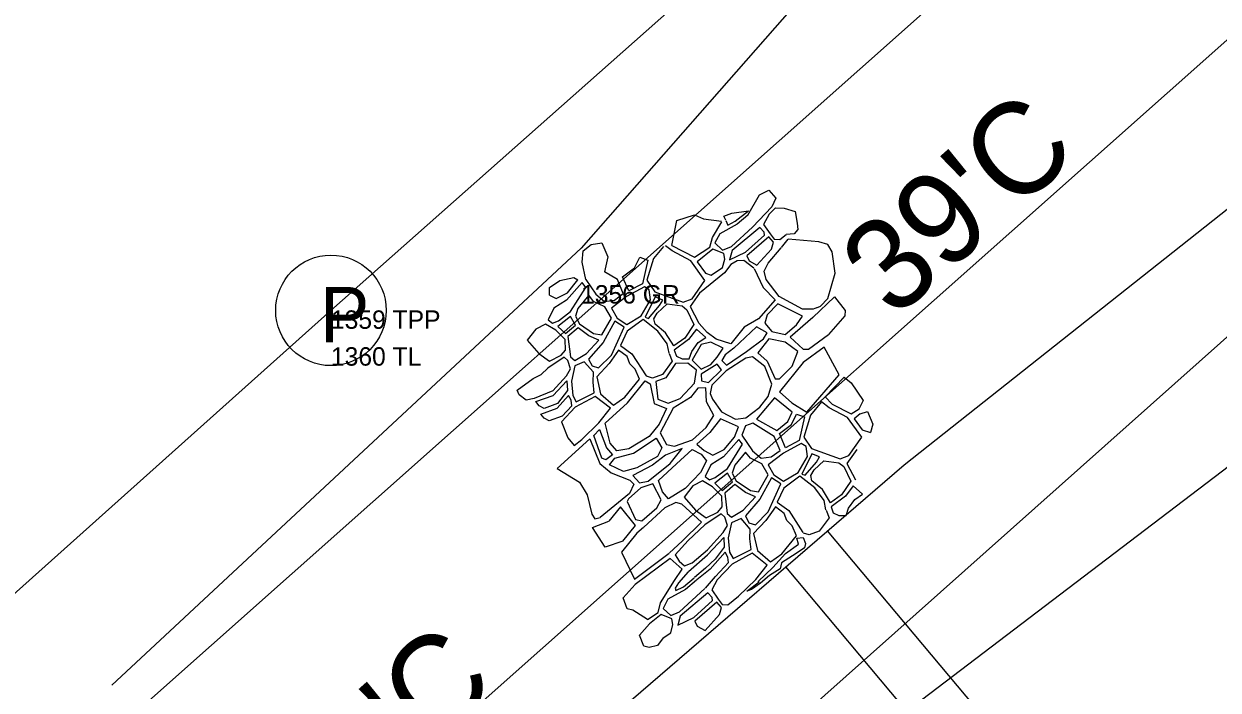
# Model space of a CAD drawing. Extents: x 50001 to 56005, y 49075 to 53926.
# Drawn here: x 53878.2 to 53943.1, y 51891.3 to 51927.5 of the extents above; entities that cross this region are included whole.
import ezdxf

# ---------------------------------------------------------------- set-up
doc = ezdxf.new("R2010")
doc.units = 0
for name, color, linetype in [('Level 1', 7, 'Continuous'), ('Level 11', 7, 'Continuous'), ('Level 16', 7, 'Continuous'), ('Level 18', 7, 'Continuous'), ('Level 3', 7, 'Continuous'), ('Level 57', 7, 'Continuous'), ('Level 59', 7, 'Continuous'), ('Level 61', 7, 'Continuous'), ('Level 7', 7, 'Continuous'), ('Level 8', 7, 'Continuous'), ('Level 9', 7, 'Continuous')]:
    doc.layers.add(name, color=color, linetype=linetype)

# ---------------------------------------------------------------- blocks, each defined once
blk = doc.blocks.new('TPP')
at = {"layer": 'Level 9'}
blk.add_circle((0, 0), 3, dxfattribs=at)
blk.add_text('P', height=3, dxfattribs=at).set_placement((-0.589, -1.729))

msp = doc.modelspace()

# ---------------------------------------------------------------- linework, layer by layer
at = {"layer": 'Level 1'}
msp.add_line((52544.807, 50683.302), (55534.583, 53340.862), dxfattribs=at)
at = {"layer": 'Level 11'}
for p, q in [((53894.91, 51911.927), (54324.203, 52292.615)), ((53424.495, 51490.929), (53894.91, 51911.927))]:
    msp.add_line(p, q, dxfattribs=at)
at = {"layer": 'Level 16'}
for p, q in [((53919.586, 51898.734), (53920.281, 51899.24)), ((53920.202, 51899.556), (53920.533, 51899.603)), ((53920.281, 51899.24), (53920.202, 51899.556)), ((53920.533, 51899.603), (53920.66, 51899.272)), ((53920.66, 51899.272), (53920.612, 51899.034)), ((53918.891, 51897.96), (53919.586, 51898.734)), ((53920.154, 51898.734), (53919.76, 51898.466)), ((53920.612, 51899.034), (53920.154, 51898.734)), ((53918.102, 51897.201), (53918.891, 51897.96)), ((53919.365, 51898.213), (53919.286, 51897.897)), ((53919.76, 51898.466), (53919.365, 51898.213)), ((53918.718, 51897.533), (53918.228, 51897.106)), ((53919.286, 51897.897), (53918.718, 51897.533)), ((53917.486, 51896.68), (53918.149, 51897.185)), ((53917.739, 51896.774), (53917.486, 51896.68)), ((53918.228, 51897.106), (53917.739, 51896.774)), ((53918.149, 51897.185), (53918.102, 51897.201))]:
    msp.add_line(p, q, dxfattribs=at)
for points in [[(53917.54, 51917.09), (53918.174, 51918.207), (53918.683, 51918.453), (53919.065, 51918.029), (53918.846, 51917.556), (53917.785, 51916.441)], [(53919.03, 51917.497), (53918.695, 51917.144), (53918.393, 51916.596), (53918.75, 51916.083), (53918.962, 51915.804), (53919.274, 51915.782), (53919.611, 51916.054)], [(53919.03, 51917.497), (53919.516, 51917.475), (53920.113, 51917.29), (53920.212, 51916.672), (53920.253, 51916.324), (53920.043, 51916.091), (53919.611, 51916.054)], [(53913.408, 51915.456), (53913.683, 51916.814), (53914.645, 51917.123), (53915.139, 51916.896), (53916.114, 51916.77)], [(53913.408, 51915.456), (53914.636, 51914.813), (53915.482, 51915.366), (53915.618, 51915.893), (53916.133, 51916.729)], [(53917.54, 51917.09), (53916.966, 51916.605), (53916.01, 51916.089), (53915.752, 51915.587), (53916.168, 51915.195), (53916.646, 51915.404), (53917.785, 51916.441)], [(53916.34, 51916.835), (53916.291, 51916.931), (53916.234, 51917.05), (53916.662, 51917.206), (53917.566, 51917.34)], [(53916.34, 51916.805), (53916.403, 51916.678), (53916.451, 51916.555), (53916.856, 51916.764), (53917.566, 51917.34)], [(53917.526, 51917.314), (53917.457, 51917.254)], [(53908.741, 51913.602), (53908.551, 51914.54), (53908.596, 51915.164), (53909.026, 51915.498), (53909.615, 51915.591), (53909.936, 51914.833), (53909.757, 51914.03)], [(53912.952, 51915.391), (53912.419, 51914.75), (53912.062, 51913.561), (53912.49, 51912.936), (53914.033, 51912.375), (53914.511, 51912.559), (53915.211, 51913.552), (53914.44, 51914.617), (53913.436, 51915.155), (53913.065, 51915.439)], [(53919.366, 51915.346), (53919.722, 51915.792)], [(53921.27, 51912.075), (53921.474, 51912.15), (53921.886, 51912.57), (53922.275, 51913.952), (53922.116, 51915.107), (53921.874, 51915.506), (53921.397, 51915.649), (53919.722, 51915.792)], [(53921.27, 51912.075), (53921.091, 51911.99), (53920.503, 51911.989), (53919.244, 51912.68), (53918.532, 51913.603), (53918.417, 51914.055), (53918.648, 51914.496), (53919.351, 51915.331)], [(53917.859, 51914.22), (53917.319, 51914.633), (53916.964, 51914.62), (53916.608, 51914.411), (53916.265, 51913.97), (53914.916, 51912.866), (53914.4, 51912.13), (53914.877, 51911.235)], [(53917.885, 51914.194), (53918.374, 51913.173), (53919.024, 51912.502), (53918.12, 51911.472), (53917.332, 51911.02), (53916.607, 51910.106), (53915.809, 51910.357), (53915.327, 51910.734), (53914.903, 51911.208)], [(53906.774, 51912.758), (53906.774, 51913.164), (53907.338, 51913.559), (53908.084, 51913.711)], [(53906.774, 51912.758), (53907.133, 51912.571), (53907.745, 51912.888), (53908.311, 51913.585)], [(53908.084, 51913.711), (53908.311, 51913.585)], [(53908.741, 51913.602), (53909.28, 51912.81), (53909.757, 51912.406), (53910.296, 51912.481), (53910.775, 51912.836), (53910.457, 51913.596), (53909.757, 51914.03)], [(53921.068, 51911.536), (53922.235, 51912.669), (53922.825, 51911.925), (53922.8, 51911.632), (53921.906, 51910.623)], [(53921.068, 51911.536), (53919.84, 51910.466), (53920.532, 51909.816), (53920.826, 51909.817), (53921.906, 51910.623)], [(53905.561, 51910.304), (53906.186, 51909.59), (53906.766, 51909.166), (53907.404, 51909.491), (53907.639, 51909.77), (53907.617, 51910.351), (53907.115, 51910.854), (53906.556, 51911.188), (53906.031, 51910.908), (53905.561, 51910.304)], [(53913.26, 51909.612), (53913.161, 51910.107), (53912.659, 51910.805), (53911.851, 51911.441), (53910.981, 51910.791), (53910.624, 51910.018), (53911.249, 51909.566), (53912.011, 51908.376)], [(53913.275, 51909.585), (53913.437, 51909.179), (53912.899, 51908.451), (53912.361, 51908.25), (53912.038, 51908.347)], [(53906.956, 51907.559), (53907.693, 51908.374), (53907.917, 51908.754), (53907.772, 51909.212), (53907.571, 51909.391), (53906.688, 51908.797), (53906.325, 51908.453)], [(53906.956, 51907.559), (53905.942, 51907.138), (53905.509, 51907.054), (53905.125, 51907.343), (53905.024, 51907.592), (53905.879, 51908.226), (53906.325, 51908.453)], [(53921.727, 51907.232), (53922.769, 51908.295), (53923.148, 51907.993), (53923.799, 51907.032), (53923.565, 51906.565)], [(53906.969, 51907.303), (53907.715, 51908.106), (53907.748, 51907.581), (53907.202, 51906.866)], [(53907.202, 51906.866), (53906.482, 51906.594), (53906.216, 51906.74), (53906.035, 51906.973), (53906.969, 51907.303)], [(53907.461, 51906.19), (53907.982, 51906.743), (53907.948, 51907.045), (53907.803, 51907.302), (53907.181, 51906.611)], [(53908.119, 51904.593), (53908.527, 51904.923), (53909.455, 51905.829), (53910.082, 51906.611), (53909.256, 51907.258), (53908.171, 51906.665), (53907.424, 51905.876)], [(53921.727, 51907.232), (53922.119, 51906.84), (53923.148, 51906.302), (53923.585, 51906.587)], [(53907.461, 51906.19), (53906.751, 51905.922), (53906.485, 51906.069), (53906.304, 51906.301), (53907.181, 51906.611)], [(53923.632, 51906.314), (53924.034, 51906.445), (53924.315, 51905.745), (53924.192, 51905.296)], [(53907.424, 51905.876), (53907.759, 51904.998), (53908.119, 51904.593)], [(53923.632, 51906.314), (53923.307, 51906.045), (53923.747, 51905.433), (53924.192, 51905.296)], [(53908.956, 51904.957), (53907.185, 51903.337), (53908.405, 51902.608), (53908.821, 51901.915), (53909.062, 51900.855), (53909.238, 51900.615), (53909.513, 51900.686)], [(53908.956, 51904.957), (53909.5, 51903.62), (53910.121, 51903.105), (53911.133, 51902.705), (53911.343, 51902.495), (53911.121, 51901.978), (53909.513, 51900.686)], [(53923.446, 51904.381), (53922.912, 51903.618), (53923.389, 51902.723)], [(53921.772, 51901.1), (53921.672, 51901.595), (53921.171, 51902.293), (53920.363, 51902.929), (53919.492, 51902.279), (53919.136, 51901.507), (53919.76, 51901.054), (53920.523, 51899.864)], [(53910.76, 51899.398), (53911.431, 51900.253), (53910.634, 51901.26), (53909.985, 51900.478)], [(53913.289, 51898.766), (53913.981, 51899.402), (53915.021, 51900.42), (53913.949, 51901.402), (53913.637, 51901.491), (53913.033, 51901.2), (53911.894, 51900.16)], [(53921.787, 51901.073), (53921.949, 51900.667), (53921.411, 51899.94), (53920.873, 51899.739), (53920.549, 51899.835)], [(53910.76, 51899.398), (53909.792, 51899.062), (53909.099, 51900.143), (53909.985, 51900.478)], [(53911.877, 51900.143), (53911.506, 51899.824), (53910.671, 51898.794), (53911.38, 51897.325), (53913.271, 51898.749)], [(53914.32, 51897.753), (53915.354, 51898.655), (53916.226, 51899.594), (53916.259, 51899.069), (53915.756, 51898.41), (53915.23, 51897.929), (53914.64, 51897.414)], [(53915.231, 51896.842), (53915.777, 51897.471), (53916.493, 51898.232), (53916.46, 51898.533), (53916.315, 51898.79), (53915.498, 51897.884), (53914.775, 51897.298)], [(53912.09, 51895.15), (53912.665, 51895.525), (53912.8, 51896.052), (53913.549, 51897.266), (53913.978, 51897.867), (53913.317, 51898.454), (53911.422, 51897.041)], [(53914.75, 51897.273), (53914.149, 51896.764), (53913.192, 51896.249), (53912.935, 51895.746), (53913.351, 51895.354), (53913.829, 51895.563), (53915.206, 51896.818)], [(53914.295, 51897.728), (53913.781, 51897.131), (53913.585, 51896.837), (53913.634, 51896.715), (53914.039, 51896.923), (53914.622, 51897.396)], [(53912.09, 51895.15), (53911.299, 51895.644), (53910.995, 51895.716), (53910.773, 51896.313), (53911.422, 51897.041)], [(53915.212, 51894.548), (53915.997, 51895.406), (53916.108, 51895.786), (53915.863, 51896.08), (53914.661, 51895.05), (53914.783, 51894.78), (53915.212, 51894.548)], [(53912.933, 51894.14), (53913.35, 51894.423), (53913.473, 51894.864), (53913.412, 51895.171), (53912.824, 51895.415), (53912.201, 51894.9)], [(53912.933, 51894.14), (53912.635, 51893.735), (53912.189, 51893.628), (53911.885, 51893.701), (53911.663, 51894.297), (53912.201, 51894.9)]]:
    msp.add_lwpolyline(points, dxfattribs=at)
for points in [[(53918.179, 51916.422), (53916.683, 51915.171), (53916.547, 51914.669), (53917.418, 51915.098), (53918.436, 51916.018), (53918.424, 51916.178)], [(53918.681, 51915.921), (53917.479, 51914.89), (53917.601, 51914.621), (53918.03, 51914.388), (53918.815, 51915.247), (53918.925, 51915.627)], [(53911.671, 51914.81), (53912.1, 51914.651), (53911.817, 51913.364), (53911.069, 51912.984), (53910.739, 51913.755), (53911.389, 51914.234)], [(53914.795, 51914.556), (53915.236, 51913.944), (53915.554, 51913.847), (53916.167, 51914.264), (53916.29, 51914.705), (53916.229, 51915.011), (53915.641, 51915.256)], [(53908.537, 51913.436), (53907.698, 51912.485), (53907.016, 51912.049), (53906.702, 51911.423), (53906.936, 51911.233), (53907.261, 51911.357), (53907.92, 51911.86), (53908.737, 51913.168)], [(53911.927, 51913.205), (53910.958, 51912.677), (53910.137, 51912.052), (53910.442, 51911.501), (53910.969, 51911.17), (53911.753, 51911.637), (53912.257, 51912.507), (53912.184, 51913.046)], [(53910.136, 51911.512), (53909.781, 51912.112), (53909.169, 51912.406), (53908.9, 51912.749), (53908.311, 51912.037), (53908.176, 51911.608), (53908.396, 51911.192), (53909.167, 51910.666), (53909.608, 51910.593)], [(53912.502, 51912.655), (53911.962, 51911.551), (53912.145, 51911.49), (53912.746, 51912.189), (53912.918, 51912.484)], [(53914.608, 51911.162), (53914.117, 51910.427), (53913.516, 51909.997), (53913.076, 51910.707), (53912.5, 51911.184), (53912.439, 51911.466), (53912.623, 51911.773), (53913.151, 51912.276), (53913.972, 51912.166), (53914.229, 51911.958)], [(53920.503, 51911.611), (53919.16, 51912.281), (53918.592, 51911.693), (53918.466, 51911.231), (53918.833, 51910.78), (53919.567, 51910.613), (53920.177, 51911.138)], [(53907.92, 51911.592), (53907.227, 51911.055), (53907.64, 51910.664), (53908.188, 51911.123)], [(53908.322, 51910.989), (53907.774, 51910.508), (53907.906, 51909.413), (53908.141, 51909.201), (53908.778, 51909.593), (53909.449, 51910.309), (53908.902, 51910.543)], [(53910.311, 51911.349), (53909.684, 51910.186), (53908.889, 51909.28), (53909.079, 51908.912), (53909.436, 51908.801), (53910.13, 51909.494), (53910.824, 51911.014)], [(53914.75, 51910.912), (53914.319, 51910.355), (53913.541, 51909.766), (53913.656, 51909.441), (53913.971, 51909.294), (53914.359, 51909.305), (53914.496, 51909.694), (53914.833, 51910.177), (53915.253, 51910.451)], [(53918.581, 51910.717), (53918.004, 51911.042), (53916.785, 51909.885), (53916.312, 51909.518), (53916.123, 51909.202), (53916.374, 51908.951), (53917.467, 51909.687), (53918.391, 51910.381)], [(53920.249, 51909.7), (53919.567, 51910.193), (53918.675, 51910.391), (53918.076, 51909.624), (53918.579, 51909.163), (53919.029, 51908.208), (53919.26, 51908.209), (53919.943, 51908.892)], [(53910.521, 51909.774), (53910.006, 51909.036), (53909.335, 51908.32), (53909.546, 51907.393), (53910.25, 51906.779), (53910.865, 51907.216), (53911.659, 51908.189), (53911.425, 51908.736), (53911.135, 51909.026), (53910.99, 51909.417)], [(53916.197, 51909.885), (53915.536, 51910.209), (53915.001, 51910.072), (53914.517, 51909.232), (53914.999, 51908.729), (53915.535, 51908.992), (53915.881, 51909.381)], [(53921.682, 51909.927), (53920.541, 51909.105), (53919.253, 51907.498), (53919.926, 51906.899), (53920.746, 51906.397), (53922.489, 51908.433)], [(53908.655, 51909.135), (53908.14, 51908.911), (53907.961, 51908.084), (53908.038, 51907.313), (53908.228, 51906.967), (53909.2, 51907.448), (53909.134, 51908.029), (53909.157, 51908.566)], [(53913.616, 51909.042), (53913.078, 51908.272), (53912.551, 51908.061), (53912.655, 51907.112), (53913.213, 51906.892), (53913.857, 51907.135), (53914.648, 51907.968), (53914.744, 51908.675), (53914.28, 51909.053)], [(53915.881, 51909.003), (53914.999, 51908.456), (53915.019, 51908.099), (53915.408, 51908.005), (53916.101, 51908.698)], [(53917.782, 51909.414), (53917.435, 51909.34), (53916.364, 51908.646), (53915.586, 51907.869), (53915.491, 51907.417), (53915.616, 51907.102), (53916.099, 51906.41), (53916.864, 51906.023), (53917.431, 51906.086), (53918.188, 51906.675), (53918.64, 51907.253), (53918.84, 51907.914), (53918.463, 51908.88)], [(53911.961, 51908.102), (53912.235, 51907.934), (53912.455, 51906.87), (53913.118, 51906.607), (53912.727, 51905.753), (53912.189, 51905.088), (53911.071, 51904.413), (53910.428, 51904.296), (53910.07, 51904.717), (53909.787, 51905.802), (53911, 51906.91)], [(53914.827, 51907.705), (53914.426, 51907.199), (53913.487, 51906.618), (53912.78, 51905.279), (53913.127, 51904.636), (53913.559, 51904.563), (53914.539, 51904.891), (53915.278, 51905.566), (53915.7, 51906.22), (53915.3, 51906.957), (53915.259, 51907.716)], [(53918.983, 51907.179), (53918.014, 51906.014), (53919.116, 51905.403), (53919.704, 51905.894), (53919.95, 51906.408)], [(53923.722, 51905.041), (53922.951, 51906.106), (53921.947, 51906.644), (53921.531, 51906.962), (53920.93, 51906.238), (53920.573, 51905.049), (53921.001, 51904.425), (53922.545, 51903.863), (53923.023, 51904.047)], [(53916.058, 51906.031), (53915.467, 51905.292), (53914.76, 51904.67), (53915.16, 51904.312), (53915.645, 51904.06), (53916.256, 51904.376), (53916.805, 51905.052), (53917.027, 51905.61)], [(53919.286, 51904.325), (53918.968, 51905.084), (53917.805, 51905.806), (53917.413, 51905.658), (53917.216, 51905.143), (53917.791, 51904.299), (53918.269, 51903.895), (53918.808, 51903.969)], [(53920.183, 51906.299), (53920.611, 51906.14), (53920.328, 51904.853), (53919.58, 51904.472), (53919.25, 51905.244), (53919.9, 51905.722)], [(53909.481, 51905.454), (53909.859, 51904.464), (53910.196, 51904.085), (53909.827, 51903.821), (53909.616, 51903.905), (53909.175, 51905.127)], [(53912.558, 51904.994), (53912.863, 51904.457), (53912.631, 51903.993), (53911.513, 51903.38), (53910.785, 51903.179), (53910.027, 51903.537), (53910.322, 51903.895), (53911.324, 51904.181)], [(53913.969, 51904.427), (53913.063, 51904.067), (53912.356, 51903.529), (53911.291, 51902.969), (53911.649, 51902.569), (53912.134, 51902.654), (53913.315, 51903.604)], [(53917.048, 51904.924), (53916.209, 51903.974), (53915.527, 51903.537), (53915.214, 51902.911), (53915.448, 51902.722), (53915.772, 51902.845), (53916.432, 51903.349), (53917.249, 51904.657)], [(53920.438, 51904.694), (53919.47, 51904.166), (53918.648, 51903.54), (53918.954, 51902.989), (53919.48, 51902.659), (53920.265, 51903.125), (53920.768, 51903.996), (53920.695, 51904.535)], [(53914.507, 51904.374), (53915.002, 51904.112), (53915.297, 51903.754), (53914.959, 51903.121), (53914.136, 51902.256), (53913.229, 51901.686), (53912.902, 51902.075), (53912.692, 51902.686), (53913.663, 51903.594)], [(53918.648, 51903.001), (53918.293, 51903.601), (53917.681, 51903.894), (53917.412, 51904.237), (53916.823, 51903.526), (53916.687, 51903.097), (53916.907, 51902.68), (53917.679, 51902.155), (53918.12, 51902.081)], [(53921.013, 51904.143), (53920.473, 51903.04), (53920.657, 51902.979), (53921.258, 51903.678), (53921.43, 51903.972)], [(53923.119, 51902.651), (53922.628, 51901.915), (53922.027, 51901.486), (53921.587, 51902.196), (53921.012, 51902.673), (53920.951, 51902.955), (53921.135, 51903.261), (53921.662, 51903.764), (53922.483, 51903.655), (53922.74, 51903.447)], [(53912.386, 51902.507), (53911.733, 51902.295), (53911.068, 51901.694), (53910.984, 51901.546), (53911.446, 51900.577), (53911.783, 51900.493), (53912.596, 51901.2), (53912.839, 51901.633)], [(53916.15, 51901.259), (53916.128, 51901.84), (53915.626, 51902.342), (53915.068, 51902.677), (53914.543, 51902.397), (53914.073, 51901.793), (53914.697, 51901.079), (53915.278, 51900.655), (53915.915, 51900.979)], [(53916.432, 51903.08), (53915.738, 51902.543), (53916.151, 51902.153), (53916.699, 51902.611)], [(53916.833, 51902.478), (53916.285, 51901.996), (53916.418, 51900.902), (53916.652, 51900.69), (53917.289, 51901.081), (53917.961, 51901.797), (53917.414, 51902.031)], [(53918.822, 51902.837), (53918.195, 51901.675), (53917.401, 51900.769), (53917.59, 51900.4), (53917.948, 51900.289), (53918.641, 51900.982), (53919.336, 51902.503)], [(53923.261, 51902.4), (53922.83, 51901.843), (53922.053, 51901.255), (53922.168, 51900.929), (53922.482, 51900.783), (53922.871, 51900.794), (53923.008, 51901.182), (53923.344, 51901.666), (53923.764, 51901.939)], [(53919.033, 51901.262), (53918.518, 51900.524), (53917.847, 51899.808), (53918.058, 51898.881), (53918.761, 51898.268), (53919.376, 51898.704), (53920.17, 51899.677), (53919.936, 51900.224), (53919.646, 51900.514), (53919.501, 51900.905)], [(53916.083, 51900.879), (53915.199, 51900.286), (53914.293, 51899.425), (53913.589, 51898.653), (53913.801, 51898.307), (53914.102, 51898.05), (53914.516, 51898.218), (53915.354, 51898.923), (53916.204, 51899.862), (53916.428, 51900.243), (53916.284, 51900.701)], [(53917.166, 51900.623), (53916.652, 51900.399), (53916.472, 51899.572), (53916.55, 51898.801), (53916.739, 51898.455), (53917.712, 51898.937), (53917.645, 51899.518), (53917.668, 51900.054)], [(53918.593, 51898.1), (53917.767, 51898.747), (53916.683, 51898.154), (53915.878, 51897.304), (53915.575, 51896.756), (53915.932, 51896.242), (53916.144, 51895.963), (53916.457, 51895.941), (53917.038, 51896.411), (53917.967, 51897.317)], [(53915.361, 51896.582), (53913.865, 51895.33), (53913.73, 51894.828), (53914.6, 51895.258), (53915.618, 51896.178), (53915.606, 51896.337)]]:
    msp.add_lwpolyline(points, close=True, dxfattribs=at)
at = {"layer": 'Level 18'}
for p, q in [((53926.024, 51903.545), (53965.282, 51934.64)), ((53891.699, 51873.945), (53926.024, 51903.545))]:
    msp.add_line(p, q, dxfattribs=at)
at = {"layer": 'Level 3'}
for p, q in [((53883.273, 51889.178), (54069.537, 52054.718)), ((53898.742, 51870.567), (54083.389, 52035.124))]:
    msp.add_line(p, q, dxfattribs=at)
at = {"layer": 'Level 7'}
for p, q in [((53934.082, 51944.47), (53908.487, 51915.299)), ((53908.487, 51915.299), (53883.022, 51891.572)), ((53922.854, 51887.665), (53958.852, 51915.059))]:
    msp.add_line(p, q, dxfattribs=at)
at = {"layer": 'Level 8'}
for p, q in [((53933.325, 51886.292), (53921.868, 51899.962)), ((53931.026, 51884.365), (53919.596, 51898.002))]:
    msp.add_line(p, q, dxfattribs=at)

# ---------------------------------------------------------------- block references
at = {"layer": 'Level 9'}
msp.add_blockref('TPP', (53894.91, 51911.927), dxfattribs=at)

# ---------------------------------------------------------------- texts
at = {"layer": 'Level 18'}
for s, rotation, p in [("39'C", 41.63335, (53925.481, 51911.392)), ("40'C", 41.63338, (53893.921, 51882.463))]:
    msp.add_text(s, height=5, rotation=rotation, dxfattribs=at).set_placement(p)
at = {"layer": 'Level 57'}
msp.add_text('1356 GR', height=1, dxfattribs=at).set_placement((53908.487, 51912.299))
at = {"layer": 'Level 59'}
msp.add_text('1359 TPP', height=1, dxfattribs=at).set_placement((53894.91, 51910.927))
at = {"layer": 'Level 61'}
msp.add_text('1360 TL', height=1, dxfattribs=at).set_placement((53894.91, 51908.927))

doc.saveas('drawing.dxf')
